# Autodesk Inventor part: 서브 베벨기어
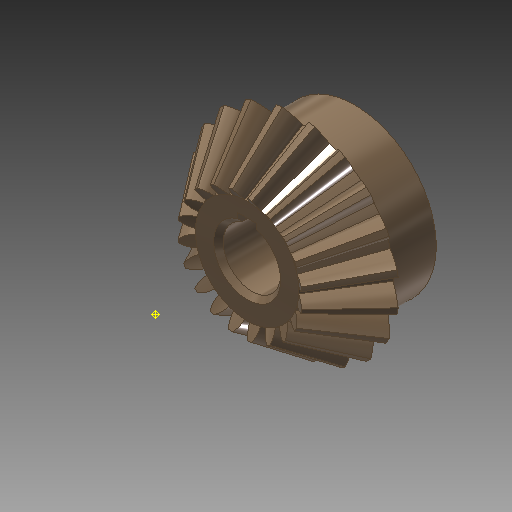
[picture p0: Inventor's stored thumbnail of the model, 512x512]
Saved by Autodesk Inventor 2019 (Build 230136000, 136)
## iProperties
Created: 2014-10
Part Number: 서브 베벨기어
Material: 강철, 탄소
Document SubType Name: Modeling
Designer: KYOUNG IL JANG
Categories: <?xml version="1.0" encoding="UTF-16"?> <MemberInstance><Categories><FamilyTemplate><FamilyTemplateParameter ValueType="xs:double" Id="1" ObjectReferenceKey="da
Mass: 135.037 g
Surface Area: 63.6518 cm^2
Volume: 17.1585 cm^3
Density: 7.87 g/cm^3
Appearance: 얼룩무늬
CustomPartVersion: 1
Revision Number: 1
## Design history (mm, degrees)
node "맨 위 점"
node "메쉬 평면2"
sketch "톱니 본체 스케치"
  geometry: L1 (0, 0)-(18.003, -31.331); L2 (18.003, -31.331)-(21.664, -28.891); L3 (21.664, -28.891)-(0, 0); L4 (20, -30)-(0, 0); L5 (10.813, -18.818)-(13.012, -17.352); L6 (18.003, -31.331)-(10.813, -18.818); L7 (21.664, -28.891)-(13.012, -17.352); L8 (0, -39.387)-(0, 6.564) reference; L9 (0, -30)-(21.664, -30)
  constraints: 16 end point, 4 point on line, 3 perpendicular, 2 collinear, 1 horizontal alignment, 1 vertical alignment
  dimensions: "d0" = 40 diameter of L4.start L8 (= da_de); "d1" = 36.00616 diameter of L1.end L8 (= da_dfe); "d2" = 43.3282 diameter of L2.end L8 (= da_dae); "d3" = 14.4 distance between parallel lines of L2 L5 (= da_b); "d4" = 28.8906 vertical distance of L2.end L1.start (= da_ve)
revolve "톱니 본체" sketch "톱니 본체 스케치" stored, may be unused: angle "d5" = 90 deg
node "시작점"
node "톱니 평면"
sketch "시작 스케치"
  geometry: L1 (0, -23.505)-(0, 10.645) reference; L2 (-0.834, -2.928)-(0.834, -2.928); A1 r 8.898 centre (-9.698, -3.713) between (-0.834, -2.928) and (-3.903, 3.04); A2 r 8.898 centre (9.698, -3.713) between (3.903, 3.04) and (0.834, -2.928); A3 r 27.357 centre (0, -24.037) between (3.903, 3.04) and (-3.903, 3.04); 1 further point
  constraints: 6 point on circle, 3 centre point, 3 symmetric about line, 2 end point, 1 coincident, 1 perpendicular, 1 other
  dimensions: "d7" = 8.89846 radius of A1 (= fd_rr); "d8" = 9.69794 horizontal distance of point (0, -24.037) A1.centre (= fd_x); "d9" = 20.32439 vertical distance of point (0, -24.037) A1.centre (= fd_y); "d57" = 27.35701 radius of A3 (= 0.5 x fd_dva + 0.3 x da_he); "d58" = 21.10901 distance from line of A3.centre L2 (= 0.5 x fd_dva - 1.12 x da_he)
node "끝점"
  node "끝 평면"
sketch "3D 스케치 오른쪽"
  node "Helical Curve Right" dims "d65" = 229.90621 (computed from da_dm, da_delta, da_beta), "d66" = 31.5, "d67" = 40 (= da_de), "d68" = -5.88003 (= -da_delta), "d69" = 12.16458 (computed from fd_loft, da_delta)
node "끝 평면 오른쪽"
sketch "끝 스케치 오른쪽"
  geometry: L1 (0, -22.649)-(0, 12.15) reference; L2 (-0.497, -1.72)-(0.497, -1.72); A1 r 5.299 centre (-5.775, -2.187) between (-0.497, -1.72) and (-2.324, 1.834); A2 r 5.299 centre (5.775, -2.187) between (2.324, 1.834) and (0.497, -1.72); A3 r 16.291 centre (0, -14.29) between (2.324, 1.834) and (-2.324, 1.834); 1 further point
  constraints: 6 point on circle, 3 centre point, 3 symmetric about line, 2 end point, 1 coincident, 1 perpendicular, 1 other
  dimensions: "d70" = 5.77526 horizontal distance of A3.centre A1.centre (computed from fd_x, fd_ratio); "d71" = 12.10346 vertical distance of point (0, -14.29) A1.centre (computed from fd_y, fd_ratio); "d72" = 5.29916 radius of A1 (computed from fd_rr, fd_ratio); "d73" = 12.57071 distance from line of point (0, -14.29) L2 (computed from d58, fd_ratio); "d74" = 16.29149 radius of A3 (computed from d57, fd_ratio)
feature "로프트 오른쪽" sketch "끝 스케치 오른쪽" dims "d75" = 0, "d77" = 0, "d79" = 0, "d80" = 90 deg, "d85" = 20, "d92" = 90 deg, "d93" = 90 deg, "da_teethtype" = 0 [user parameter]
sketch "3D 스케치 왼쪽"
  node "Helical Curve Left" dims "d26" = 229.90621 (computed from da_dm, da_delta, da_beta), "d27" = 12.16458 (computed from fd_loft, da_delta), "d28" = 40 (= da_de), "d29" = -5.88003 (= -da_delta)
node "끝 평면 왼쪽"
sketch "끝 스케치 왼쪽" dims "d56" = 10.82768 (derived)
  geometry: L1 (0, -35.087)-(0, 18.089) reference; L2 (-0.497, -1.716)-(0.497, -1.716); A1 r 5.299 centre (-5.775, -2.183) between (-0.497, -1.716) and (-2.324, 1.838); A2 r 5.299 centre (5.775, -2.183) between (2.324, 1.838) and (0.497, -1.716); A3 r 16.291 centre (0, -14.287) between (2.324, 1.838) and (-2.324, 1.838); 2 further points; 1 other entity
  constraints: 6 point on circle, 3 centre point, 3 symmetric about line, 2 end point, 1 coincident, 2 other
  dimensions: "d30" = 5.29916 radius of A1 (computed from fd_rr, fd_ratio); "d31" = 5.77526 horizontal distance of point (0, -14.287) A1.centre (computed from fd_x, fd_ratio); "d32" = 12.10346 vertical distance of A1.centre point (0, -14.287) (computed from fd_y, fd_ratio); "d61" = 16.29149 radius of A3 (computed from d57, fd_ratio); "d62" = 12.57071 distance from line of point (0, -14.287) L2 (computed from d58, fd_ratio)
feature "로프트 왼쪽" sketch "끝 스케치 왼쪽" dims "d35" = 0, "d37" = 0, "d39" = 0, "d40" = 90 deg, "d84" = 10, "d90" = 90 deg, "d91" = 90 deg, "da_teethtype" = 0 [user parameter]
sketch "본체 스케치"
  geometry: L1 (0, -35.038)-(0, -19.531) reference; L2 (18.003, -31.331)-(10.813, -18.818) reference; L3 (10.813, -18.818)-(0, -18.818); L4 (18.003, -31.331)-(0, -31.331)
  constraints: 4 end point, 2 perpendicular, 2 point on line
revolve "본체 고정" sketch "본체 스케치" stored, may be unused: angle "d46" = 90 deg
feature "피치 지름" dims angle "d47" = 90 deg
sketch "스케치8"
  geometry: C1 r 17 at (0, 0); 1 further point
  constraints: 1 centre point, 1 coincident
  dimensions: "d94" = 34 diameter of C1
extrude "돌출1" join sketch "스케치8" distance "d95" = 10; taper "d96" = 0 deg
sketch "스케치9"
  geometry: 1 further point
hole "구멍1" sketch "스케치9" at (0, 0) diameter "d97" = 12; stored, may be unused: countersink angle "d101" = 90 deg, drill point angle "d103" = 118 deg; dims "d98" = 6, "d99" = 4, "d100" = 2, "d102" = 8
sketch "스케치10"
  geometry: 1 further point
sketch "스케치11"
  geometry: 1 further point
sketch "스케치12"
  geometry: L1 (-2, 5.657)-(-2, 7.8); L2 (-2, 7.8)-(2, 7.8); L3 (2, 7.8)-(2, 5.657); A1 r 6 centre (0, 0) between (-2, 5.657) and (2, 5.657) reference; 1 further point
  constraints: 6 end point, 2 parallel, 2 point on circle, 1 perpendicular, 1 vertical
  dimensions: "d104" = 4 distance of L1.end L2.end; "d105" = 13.8 dimension on A1 L2
extrude "돌출2" cut sketch "스케치12" extent not by distance; stored distance "d106" = 7; taper "d107" = 0 deg
chamfer "모따기1" distance "d108" = 1; stored, may be unused: second distance "d109" = 2, angle "d110" = 45 deg
body "Solid1"
feature "로프트" dims "d17" = 0, "d18" = 90 deg, "d19" = 0, "d20" = 90 deg, "d89" = 0, "da_teethtype" = 0 [user parameter]
pattern_circular "원형 패턴" dims angle "d22" = 360 deg, "d88" = 0, "da_teethtype" = 0 [user parameter]
pattern_circular "원형 패턴 오른쪽" dims angle "d82" = 360 deg, "da_teethtype" = 0 [user parameter]
pattern_circular "원형 패턴 왼쪽" dims angle "d42" = 360 deg, "da_teethtype" = 0 [user parameter]
sketch "끝 스케치"
  geometry: L1 (0, -15.359)-(0, 6.983) reference; L2 (-0.497, -1.72)-(0.497, -1.72); A1 r 5.299 centre (-5.775, -2.187) between (-0.497, -1.72) and (-2.324, 1.834); A2 r 5.299 centre (5.775, -2.187) between (2.324, 1.834) and (0.497, -1.72); A3 r 16.291 centre (0, -14.29) between (2.324, 1.834) and (-2.324, 1.834); 1 further point
  constraints: 6 point on circle, 3 centre point, 3 symmetric about line, 2 end point, 1 coincident, 1 other
  dimensions: "d12" = 5.29916 radius of A1 (computed from fd_rr, fd_ratio); "d15" = 5.77526 horizontal distance of A1.centre point (0, -14.29) (computed from fd_x, fd_ratio); "d16" = 12.10346 vertical distance of A1.centre point (0, -14.29) (computed from fd_y, fd_ratio); "d59" = 16.29149 radius of A3 (computed from d57, fd_ratio); "d60" = 12.57071 distance from line of A3.centre L2 (computed from d58, fd_ratio)
sketch "Sketch6"
  geometry: L1 (20, -30)-(0, 0) reference; L2 (0, -37.8)-(0, 6.3) reference
body "Srf1"
other parameters: "da_b" = 14.4 [user parameter; used in 2 equation terms], "da_de" = 40 [user parameter; used in 4 equation terms], "da_dae" = 43.3282 [user parameter; used in 2 equation terms], "da_dfe" = 36.00616 [user parameter; used in 1 equation term], "da_le" = 36.05551 [user parameter; used in 1 equation term], "da_omega" = 90 deg [user parameter; used in 1 equation term], "da_beta" = 0 [user parameter; used in 2 equation terms], "da_delta" = 5.88003 [user parameter; used in 8 equation terms], "da_alpha" = 20 deg [user parameter; used in 2 equation terms], "da_he" = 4.4 [user parameter; used in 4 equation terms], "da_ve" = 28.8906 [user parameter; used in 1 equation term], "fd_dv" = 48.07402 (computed from da_de, da_delta) [user parameter; used in 1 equation term], "fd_dva" = 52.07402 (computed from da_dae, da_delta) [user parameter; used in 3 equation terms], "fd_dvb" = 45.1748 (computed from fd_dv, da_alpha) [user parameter; used in 2 equation terms], "da_zv" = 240.37008 [user parameter; used in 1 equation term], "fd_loft" = 14.62 (= da_b + 0.05 x da_he) [user parameter; used in 4 equation terms], "fd_ratio" = 5.95514 (computed from da_le, fd_loft) [user parameter; used in 15 equation terms], "fd_rr" = 8.89846 (computed from fd_dd, fd_dvb) [user parameter; used in 6 equation terms], "fd_angle" = 0.66075 (computed from da_zv) [user parameter; used in 4 equation terms], "fd_x1" = 1.58709 (computed from da_dvw, fd_angle) [user parameter; used in 1 equation term], "fd_y1" = 23.98456 (computed from da_dvw, fd_angle) [user parameter; used in 1 equation term], "fd_x2" = 8.11084 (computed from fd_rr, fd_angle2, fd_angle) [user parameter; used in 1 equation term], "fd_y2" = 3.66016 (computed from fd_rr, fd_angle2, fd_angle) [user parameter; used in 1 equation term], "fd_x" = 9.69794 (= fd_x1 + fd_x2) [user parameter; used in 4 equation terms], "fd_y" = 20.32439 (= fd_y1 - fd_y2) [user parameter; used in 4 equation terms], "fd_angle2" = 3.57832 (computed from fd_dvb, fd_dd, da_alpha) [user parameter; used in 2 equation terms], "fd_dd" = 48.55402 (= fd_dva - 0.8 x da_he) [user parameter; used in 2 equation terms], "da_dvw" = 48.07402 [user parameter; used in 2 equation terms], "d11" = 14.62 (= fd_loft), "da_dm" = 32.01232 [user parameter; used in 2 equation terms], "da_x" = 0 [user parameter], "da_m" = 2 [user parameter], "d48" = 0, "d49" = 0, "d50" = 90 deg (= da_omega), "d51" = 9 deg (computed from da_z), "d52" = 0, "d53" = 0, "d54" = 0
